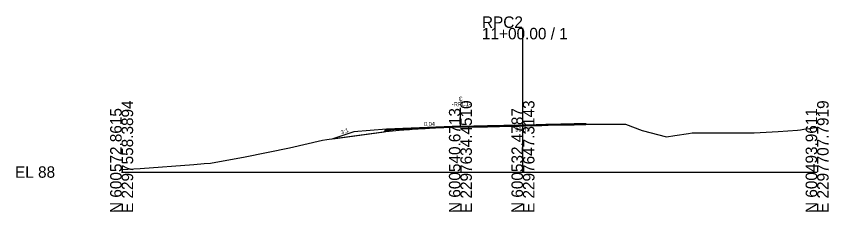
# Model space of a CAD drawing. Extents: x 2124 to 2376, y -10 to 1517.
# Drawn here: x 2124.3 to 2322.4, y -9.7 to 38 of the extents above; entities that cross this region are included whole.
import ezdxf

# ---------------------------------------------------------------- set-up
doc = ezdxf.new("R2010")
doc.units = 0
for name, color, linetype in [('Exist Cross Section Cell', 7, 'Continuous'), ('Exist XS Center Line Elevation Label', 7, 'Continuous'), ('Exist XS Ground Line', 7, 'Continuous'), ('Prop CMT Pvmt Course 3 Wedge', 7, 'Continuous'), ('Prop CMT Pvmt Surface', 7, 'Continuous'), ('Prop CMT Pvmt Surface Overlay', 7, 'Continuous'), ('Prop CMT Shld Paved Course 1', 7, 'Continuous'), ('Prop CMT Shld Paved Course 2', 7, 'Continuous'), ('Prop CMT Slope Grass', 7, 'Continuous'), ('Prop XS Earthwork Shape', 7, 'Continuous'), ('Prop XS Label Text', 7, 'Continuous'), ('Prop XS SE Text', 7, 'Continuous'), ('Prop XS Side Slope Text', 7, 'Continuous')]:
    doc.layers.add(name, color=color, linetype=linetype)

msp = doc.modelspace()

# ---------------------------------------------------------------- linework, layer by layer
at = {"layer": 'Exist Cross Section Cell'}
for p, q in [((2247.84, 0), (2247.84, 35.18)), ((2150, 0), (2232.59, 0)), ((2232.59, 0), (2247.84, 0)), ((2247.84, 0), (2319.55, 0))]:
    msp.add_line(p, q, dxfattribs=at)
at = {"layer": 'Exist XS Ground Line'}
msp.add_lwpolyline([(2150, 0.62), (2154.52, 0.88), (2167.59, 1.85), (2170.15, 2.07), (2171.7, 2.18), (2180.1, 3.75), (2190.96, 5.92), (2198.93, 7.81), (2200.04, 7.94), (2214.39, 9.91), (2218.47, 10.28), (2218.82, 10.31), (2219.62, 10.37), (2220.17, 10.41), (2221.49, 10.51), (2222.33, 10.57), (2223.99, 10.66), (2225.04, 10.72), (2225.89, 10.76), (2227.9, 10.85), (2230.47, 10.95), (2232.59, 11.04), (2233.48, 11.08), (2234.27, 11.1), (2235.27, 11.13), (2235.64, 11.13), (2236.21, 11.14), (2238.5, 11.18), (2239.17, 11.2), (2240.36, 11.23), (2242.14, 11.26), (2243.15, 11.28), (2244.34, 11.3), (2245.1, 11.32), (2246.15, 11.34), (2246.88, 11.35), (2247.82, 11.37), (2248.52, 11.38), (2251.03, 11.44), (2251.58, 11.46), (2252.46, 11.49), (2253.39, 11.53), (2253.99, 11.54), (2257.11, 11.61), (2258.83, 11.66), (2259.24, 11.67), (2260.34, 11.69), (2260.73, 11.7), (2262.38, 11.73), (2263.12, 11.72), (2272.81, 11.66), (2276.93, 10.15), (2282.79, 8.56), (2284.89, 8.95), (2288.17, 9.42), (2289.06, 9.57), (2302.25, 9.55), (2304.24, 9.56), (2310.03, 9.93), (2314.73, 10.21), (2315.53, 10.34), (2316.28, 10.47), (2317.67, 10.66), (2319.55, 10.94)], dxfattribs=at)
at = {"layer": 'Prop CMT Pvmt Course 3 Wedge'}
msp.add_line((2214.09, 9.97), (2213.97, 9.85), dxfattribs=at)
at = {"layer": 'Prop CMT Pvmt Surface'}
for p, q in [((2215.72, 10.03), (2214.08, 9.96)), ((2232.59, 10.95), (2214.35, 10.22)), ((2232.59, 11.2), (2214.61, 10.48)), ((2232.59, 11.2), (2235.84, 11.26)), ((2232.59, 10.95), (2235.84, 11.01)), ((2263.16, 11.84), (2263.16, 11.59))]:
    msp.add_line(p, q, dxfattribs=at)
for points in [[(2235.84, 11.26), (2236.21, 11.26), (2238.5, 11.31), (2239.17, 11.32), (2240.36, 11.35), (2242.14, 11.39), (2243.15, 11.41), (2244.34, 11.43), (2245.1, 11.44), (2246.15, 11.46), (2246.88, 11.47), (2247.82, 11.5), (2248.52, 11.51), (2251.03, 11.57), (2251.58, 11.58), (2252.46, 11.61), (2253.39, 11.65), (2253.99, 11.66), (2257.11, 11.74), (2258.83, 11.79), (2259.24, 11.8), (2260.34, 11.81), (2260.73, 11.83), (2262.38, 11.85), (2263.16, 11.84)], [(2235.84, 11.01), (2236.21, 11.01), (2238.5, 11.06), (2239.17, 11.07), (2240.36, 11.1), (2242.14, 11.14), (2243.15, 11.16), (2244.34, 11.18), (2245.1, 11.19), (2246.15, 11.21), (2246.88, 11.22), (2247.82, 11.25), (2248.52, 11.26), (2251.03, 11.32), (2251.58, 11.33), (2252.46, 11.36), (2253.39, 11.4), (2253.99, 11.41), (2257.11, 11.49), (2258.83, 11.54), (2259.24, 11.55), (2260.34, 11.56), (2260.73, 11.58), (2262.38, 11.6), (2263.16, 11.59)]]:
    msp.add_lwpolyline(points, dxfattribs=at)
at = {"layer": 'Prop CMT Pvmt Surface Overlay'}
for p, q in [((2232.59, 10.95), (2214.35, 10.22)), ((2232.59, 11.2), (2214.61, 10.48)), ((2232.59, 11.2), (2235.84, 11.26)), ((2232.59, 10.95), (2235.84, 11.01)), ((2235.84, 11.26), (2235.84, 11.01)), ((2263.16, 11.84), (2263.16, 11.59))]:
    msp.add_line(p, q, dxfattribs=at)
for points in [[(2235.84, 11.26), (2236.21, 11.26), (2238.5, 11.31), (2239.17, 11.32), (2240.36, 11.35), (2242.14, 11.39), (2243.15, 11.41), (2244.34, 11.43), (2245.1, 11.44), (2246.15, 11.46), (2246.88, 11.47), (2247.82, 11.5), (2248.52, 11.51), (2251.03, 11.57), (2251.58, 11.58), (2252.46, 11.61), (2253.39, 11.65), (2253.99, 11.66), (2257.11, 11.74), (2258.83, 11.79), (2259.24, 11.8), (2260.34, 11.81), (2260.73, 11.83), (2262.38, 11.85), (2263.16, 11.84)], [(2235.84, 11.01), (2236.21, 11.01), (2238.5, 11.06), (2239.17, 11.07), (2240.36, 11.1), (2242.14, 11.14), (2243.15, 11.16), (2244.34, 11.18), (2245.1, 11.19), (2246.15, 11.21), (2246.88, 11.22), (2247.82, 11.25), (2248.52, 11.26), (2251.03, 11.32), (2251.58, 11.33), (2252.46, 11.36), (2253.39, 11.4), (2253.99, 11.41), (2257.11, 11.49), (2258.83, 11.54), (2259.24, 11.55), (2260.34, 11.56), (2260.73, 11.58), (2262.38, 11.6), (2263.16, 11.59)]]:
    msp.add_lwpolyline(points, dxfattribs=at)
at = {"layer": 'Prop CMT Shld Paved Course 1'}
msp.add_lwpolyline([(2214.61, 10.48), (2214.35, 10.22)], dxfattribs=at)
at = {"layer": 'Prop CMT Shld Paved Course 2'}
msp.add_line((2215.72, 10.03), (2214.08, 9.96), dxfattribs=at)
msp.add_lwpolyline([(2214.35, 10.23), (2214.08, 9.96)], dxfattribs=at)
at = {"layer": 'Prop CMT Slope Grass'}
for p, q in [((2214.61, 10.48), (2206.61, 9.84)), ((2214.61, 10.48), (2213.97, 9.85)), ((2206.61, 9.84), (2201.5, 8.14))]:
    msp.add_line(p, q, dxfattribs=at)
at = {"layer": 'Prop XS Earthwork Shape'}
msp.add_lwpolyline([(2201.5, 8.14), (2213.97, 9.85), (2214.61, 10.48), (2206.61, 9.84)], close=True, dxfattribs=at)
at = {"layer": 'Prop XS Label Text'}
msp.add_line((2232.59, 11.2), (2232.59, 15.65), dxfattribs=at)

# ---------------------------------------------------------------- texts
at = {"layer": 'Exist Cross Section Cell'}
for s, p in [('RPC2', (2237.84, 35.18)), ('11+00.00 / 1', (2237.84, 32.38)), ('EL 88', (2124, -1.4))]:
    msp.add_text(s, height=2.8, dxfattribs=at).set_placement(p)
for s, p in [('E 2297558.3894', (2152.8, -10)), ('E 2297634.4510', (2235.39, -10)), ('E 2297647.3143', (2250.64, -10)), ('E 2297707.7919', (2322.35, -10)), ('N 600572.8615', (2150, -10)), ('N 600540.6713', (2232.59, -10)), ('N 600532.4787', (2247.84, -10)), ('N 600493.9611', (2319.55, -10))]:
    msp.add_text(s, height=2.8, rotation=90, dxfattribs=at).set_placement(p)
at = {"layer": 'Exist XS Center Line Elevation Label'}
msp.add_text('99.37', height=1, dxfattribs=at).set_placement((2245.97, 9.87))
at = {"layer": 'Prop XS Label Text'}
for s, p in [('C', (2232.15, 17.38)), ('L', (2232.42, 17.06)), ('-RPC1-', (2230.5, 16.07))]:
    msp.add_text(s, height=1, dxfattribs=at).set_placement(p)
at = {"layer": 'Prop XS SE Text'}
msp.add_text('0.04', height=1, rotation=0.8783, dxfattribs=at).set_placement((2223.7, 11.21))
at = {"layer": 'Prop XS Side Slope Text'}
msp.add_text('3:1', height=1, rotation=20.6597, dxfattribs=at).set_placement((2203.64, 9.16))

doc.saveas('drawing.dxf')
